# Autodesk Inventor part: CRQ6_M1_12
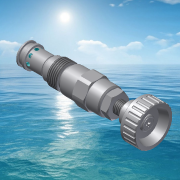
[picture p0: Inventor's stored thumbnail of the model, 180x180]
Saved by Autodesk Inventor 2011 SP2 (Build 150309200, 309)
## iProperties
Created: 2014-06
Part Number: CRQ6_M1_12
Document SubType Name: Modeling
Designer: dorohin
Density: 1 g/cm^3
Author: dorohin
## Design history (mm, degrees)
derived "CRQ6_M1_12.iam"
node "Твердое тело1"
node "0112702.ipt:1"
node "0122447-01(PT).ipt:1"
node "0112816.ipt:1"
node "0112703.ipt:1"
node "0632044.ipt:1"
node "0112745.ipt:1"
node "0731083.ipt:1"
node "0112704.ipt:1"
node "0532040.ipt:1"
node "0112827.ipt:1"
